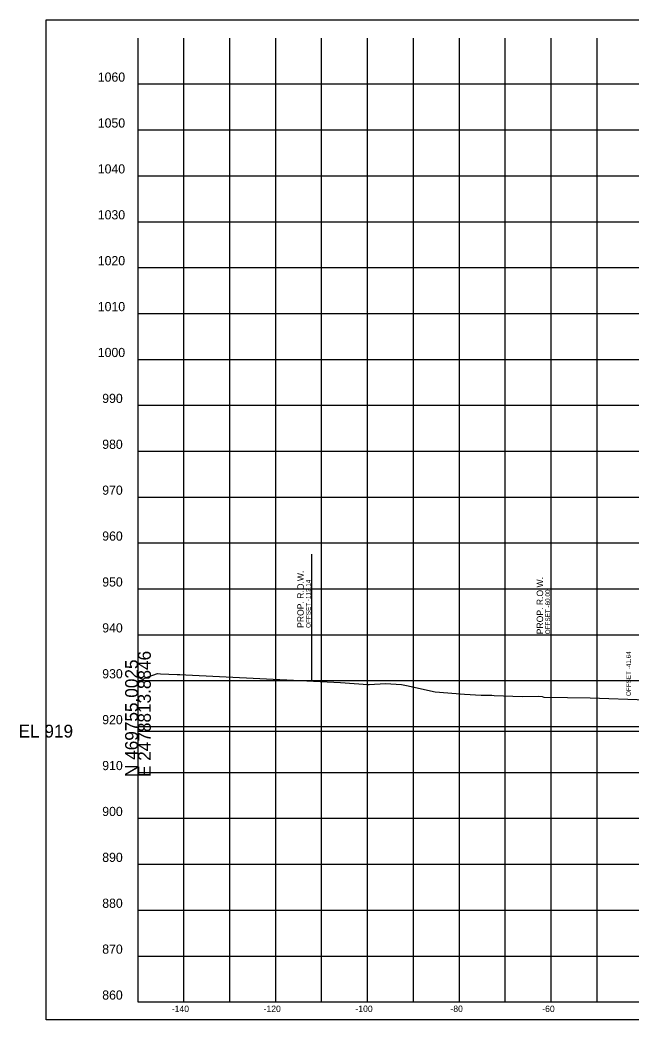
# Model space of a CAD drawing. Extents: x -26 to 2478923, y -10 to 469990.
# Drawn here: x -25.7 to 107.6, y 3437.1 to 3654.9 of the extents above; entities that cross this region are included whole.
import ezdxf

# ---------------------------------------------------------------- set-up
doc = ezdxf.new("R2010")
doc.units = 0
for name, color, linetype in [('DESIGN - ROW - Right-of-Way and Easement Labels', 7, 'Continuous'), ('DESIGN - ROW - Right-of-Way Linework', 7, 'Continuous'), ('DESIGN - SHEET - Corner Text', 7, 'Continuous'), ('DESIGN - SHEET - Light Grid', 7, 'Continuous'), ('DESIGN - SHEET - Linework', 7, 'Continuous'), ('DESIGN - SHEET - Plot Shape', 7, 'Continuous'), ('DESIGN - TYPICAL - Slope Tie Text', 7, 'Continuous'), ('SURVEY - GROUND - Top of Ground', 7, 'Continuous')]:
    doc.layers.add(name, color=color, linetype=linetype)

msp = doc.modelspace()

# ---------------------------------------------------------------- linework, layer by layer
at = {"layer": 'DESIGN - ROW - Right-of-Way Linework'}
for p, q in [((37.86, 3510.88), (37.86, 3538.56)), ((90, 3507.36), (90, 3537.04))]:
    msp.add_line(p, q, dxfattribs=at)
at = {"layer": 'DESIGN - SHEET - Light Grid'}
msp.add_line((0, 3500), (150, 3500), dxfattribs=at)
at = {"layer": 'DESIGN - SHEET - Linework'}
for p, q in [((10, 3441), (10, 3651)), ((10, 3441), (10, 3651)), ((10, 3441), (10, 3651)), ((10, 3441), (10, 3651)), ((20, 3441), (20, 3651)), ((20, 3441), (20, 3651)), ((20, 3441), (20, 3651)), ((20, 3441), (20, 3651)), ((30, 3441), (30, 3651)), ((30, 3441), (30, 3651)), ((30, 3441), (30, 3651)), ((30, 3441), (30, 3651)), ((40, 3441), (40, 3651)), ((40, 3441), (40, 3651)), ((40, 3441), (40, 3651)), ((40, 3441), (40, 3651)), ((50, 3441), (50, 3651)), ((50, 3441), (50, 3651)), ((50, 3441), (50, 3651)), ((50, 3441), (50, 3651)), ((60, 3441), (60, 3651)), ((60, 3441), (60, 3651)), ((60, 3441), (60, 3651)), ((60, 3441), (60, 3651)), ((70, 3441), (70, 3651)), ((70, 3441), (70, 3651)), ((70, 3441), (70, 3651)), ((70, 3441), (70, 3651)), ((80, 3441), (80, 3651)), ((80, 3441), (80, 3651)), ((80, 3441), (80, 3651)), ((80, 3441), (80, 3651)), ((90, 3441), (90, 3651)), ((90, 3441), (90, 3651)), ((90, 3441), (90, 3651)), ((90, 3441), (90, 3651)), ((100, 3441), (100, 3651)), ((100, 3441), (100, 3651)), ((100, 3441), (100, 3651)), ((100, 3441), (100, 3651)), ((0, 3641), (300, 3641)), ((0, 3641), (300, 3641)), ((0, 3641), (300, 3641)), ((0, 3641), (300, 3641)), ((0, 3631), (300, 3631)), ((0, 3631), (300, 3631)), ((0, 3631), (300, 3631)), ((0, 3631), (300, 3631)), ((0, 3621), (300, 3621)), ((0, 3621), (300, 3621)), ((0, 3621), (300, 3621)), ((0, 3621), (300, 3621)), ((0, 3611), (300, 3611)), ((0, 3611), (300, 3611)), ((0, 3611), (300, 3611)), ((0, 3611), (300, 3611)), ((0, 3601), (300, 3601)), ((0, 3601), (300, 3601)), ((0, 3601), (300, 3601)), ((0, 3601), (300, 3601)), ((0, 3591), (300, 3591)), ((0, 3591), (300, 3591)), ((0, 3591), (300, 3591)), ((0, 3591), (300, 3591)), ((0, 3581), (300, 3581)), ((0, 3581), (300, 3581)), ((0, 3581), (300, 3581)), ((0, 3581), (300, 3581)), ((0, 3571), (300, 3571)), ((0, 3571), (300, 3571)), ((0, 3571), (300, 3571)), ((0, 3571), (300, 3571)), ((0, 3561), (300, 3561)), ((0, 3561), (300, 3561)), ((0, 3561), (300, 3561)), ((0, 3561), (300, 3561)), ((0, 3551), (300, 3551)), ((0, 3551), (300, 3551)), ((0, 3551), (300, 3551)), ((0, 3551), (300, 3551)), ((0, 3541), (300, 3541)), ((0, 3541), (300, 3541)), ((0, 3541), (300, 3541)), ((0, 3541), (300, 3541)), ((0, 3531), (300, 3531)), ((0, 3531), (300, 3531)), ((0, 3531), (300, 3531)), ((0, 3531), (300, 3531)), ((0, 3521), (300, 3521)), ((0, 3521), (300, 3521)), ((0, 3521), (300, 3521)), ((0, 3521), (300, 3521)), ((0, 3511), (300, 3511)), ((0, 3511), (300, 3511)), ((0, 3511), (300, 3511)), ((0, 3511), (300, 3511)), ((0, 3501), (300, 3501)), ((0, 3501), (300, 3501)), ((0, 3501), (300, 3501)), ((0, 3501), (300, 3501)), ((0, 3491), (300, 3491)), ((0, 3491), (300, 3491)), ((0, 3491), (300, 3491)), ((0, 3491), (300, 3491)), ((0, 3481), (300, 3481)), ((0, 3481), (300, 3481)), ((0, 3481), (300, 3481)), ((0, 3481), (300, 3481)), ((0, 3471), (300, 3471)), ((0, 3471), (300, 3471)), ((0, 3471), (300, 3471)), ((0, 3471), (300, 3471)), ((0, 3461), (300, 3461)), ((0, 3461), (300, 3461)), ((0, 3461), (300, 3461)), ((0, 3461), (300, 3461)), ((0, 3451), (300, 3451)), ((0, 3451), (300, 3451)), ((0, 3451), (300, 3451)), ((0, 3451), (300, 3451))]:
    msp.add_line(p, q, dxfattribs=at)
msp.add_lwpolyline([(0, 3651), (0, 3441), (300, 3441), (300, 3651)], dxfattribs=at)
msp.add_lwpolyline([(0, 3651), (0, 3441), (300, 3441), (300, 3651)], dxfattribs=at)
msp.add_lwpolyline([(0, 3651), (0, 3441), (300, 3441), (300, 3651)], dxfattribs=at)
msp.add_lwpolyline([(0, 3651), (0, 3441), (300, 3441), (300, 3651)], dxfattribs=at)
at = {"layer": 'DESIGN - SHEET - Plot Shape'}
msp.add_lwpolyline([(-20, 3654.94), (320, 3654.94), (320, 3437.06), (-20, 3437.06)], close=True, dxfattribs=at)
msp.add_lwpolyline([(-20, 3654.94), (320, 3654.94), (320, 3437.06), (-20, 3437.06)], close=True, dxfattribs=at)
msp.add_lwpolyline([(-20, 3654.94), (320, 3654.94), (320, 3437.06), (-20, 3437.06)], close=True, dxfattribs=at)
msp.add_lwpolyline([(-20, 3654.94), (320, 3654.94), (320, 3437.06), (-20, 3437.06)], close=True, dxfattribs=at)
at = {"layer": 'SURVEY - GROUND - Top of Ground'}
msp.add_line((10.46, 3512.27), (44.08, 3510.56), dxfattribs=at)
for points in [[(0, 3511.78), (1.14, 3511.23), (1.44, 3511.54), (4.22, 3512.52), (4.91, 3512.49), (8.56, 3512.35), (9.1, 3512.32), (10.46, 3512.27)], [(44.08, 3510.56), (50.04, 3510.14), (50.36, 3510.16), (53.9, 3510.35), (57.39, 3510.17), (58.48, 3509.94), (64.7, 3508.58), (71.11, 3508.03), (74.73, 3507.86), (77.06, 3507.82), (77.59, 3507.79), (83.71, 3507.55), (87.32, 3507.61), (88.01, 3507.58), (88.37, 3507.37), (93.55, 3507.36), (98.52, 3507.24), (110.74, 3506.8)]]:
    msp.add_lwpolyline(points, dxfattribs=at)

# ---------------------------------------------------------------- texts
at = {"layer": 'DESIGN - ROW - Right-of-Way and Easement Labels'}
for s, height, p in [('PROP. R.O.W.', 1.4, (36.11, 3522.49)), ('OFFSET -112.14', 1, (37.61, 3522.49)), ('PROP. R.O.W.', 1.4, (88.25, 3521.1)), ('OFFSET -60.00', 1, (89.75, 3521.1))]:
    msp.add_text(s, height=height, rotation=90, dxfattribs=at).set_placement(p)
at = {"layer": 'DESIGN - SHEET - Corner Text'}
for s, height, p in [('1060', 2, (-8.75, 3641.5)), ('1060', 2, (-8.75, 3641.5)), ('1060', 2, (-8.75, 3641.5)), ('1060', 2, (-8.75, 3641.5)), ('1050', 2, (-8.75, 3631.5)), ('1050', 2, (-8.75, 3631.5)), ('1050', 2, (-8.75, 3631.5)), ('1050', 2, (-8.75, 3631.5)), ('1040', 2, (-8.75, 3621.5)), ('1040', 2, (-8.75, 3621.5)), ('1040', 2, (-8.75, 3621.5)), ('1040', 2, (-8.75, 3621.5)), ('1030', 2, (-8.75, 3611.5)), ('1030', 2, (-8.75, 3611.5)), ('1030', 2, (-8.75, 3611.5)), ('1030', 2, (-8.75, 3611.5)), ('1020', 2, (-8.75, 3601.5)), ('1020', 2, (-8.75, 3601.5)), ('1020', 2, (-8.75, 3601.5)), ('1020', 2, (-8.75, 3601.5)), ('1010', 2, (-8.75, 3591.5)), ('1010', 2, (-8.75, 3591.5)), ('1010', 2, (-8.75, 3591.5)), ('1010', 2, (-8.75, 3591.5)), ('1000', 2, (-8.75, 3581.5)), ('1000', 2, (-8.75, 3581.5)), ('1000', 2, (-8.75, 3581.5)), ('1000', 2, (-8.75, 3581.5)), ('990', 2, (-7.78, 3571.5)), ('990', 2, (-7.78, 3571.5)), ('990', 2, (-7.78, 3571.5)), ('990', 2, (-7.78, 3571.5)), ('980', 2, (-7.78, 3561.5)), ('980', 2, (-7.78, 3561.5)), ('980', 2, (-7.78, 3561.5)), ('980', 2, (-7.78, 3561.5)), ('970', 2, (-7.78, 3551.5)), ('970', 2, (-7.78, 3551.5)), ('970', 2, (-7.78, 3551.5)), ('970', 2, (-7.78, 3551.5)), ('960', 2, (-7.78, 3541.5)), ('960', 2, (-7.78, 3541.5)), ('960', 2, (-7.78, 3541.5)), ('960', 2, (-7.78, 3541.5)), ('950', 2, (-7.78, 3531.5)), ('950', 2, (-7.78, 3531.5)), ('950', 2, (-7.78, 3531.5)), ('950', 2, (-7.78, 3531.5)), ('940', 2, (-7.78, 3521.5)), ('940', 2, (-7.78, 3521.5)), ('940', 2, (-7.78, 3521.5)), ('940', 2, (-7.78, 3521.5)), ('930', 2, (-7.78, 3511.5)), ('930', 2, (-7.78, 3511.5)), ('930', 2, (-7.78, 3511.5)), ('930', 2, (-7.78, 3511.5)), ('920', 2, (-7.78, 3501.5)), ('920', 2, (-7.78, 3501.5)), ('920', 2, (-7.78, 3501.5)), ('920', 2, (-7.78, 3501.5)), ('910', 2, (-7.78, 3491.5)), ('910', 2, (-7.78, 3491.5)), ('910', 2, (-7.78, 3491.5)), ('910', 2, (-7.78, 3491.5)), ('900', 2, (-7.78, 3481.5)), ('900', 2, (-7.78, 3481.5)), ('900', 2, (-7.78, 3481.5)), ('900', 2, (-7.78, 3481.5)), ('890', 2, (-7.78, 3471.5)), ('890', 2, (-7.78, 3471.5)), ('890', 2, (-7.78, 3471.5)), ('890', 2, (-7.78, 3471.5)), ('880', 2, (-7.78, 3461.5)), ('880', 2, (-7.78, 3461.5)), ('880', 2, (-7.78, 3461.5)), ('880', 2, (-7.78, 3461.5)), ('870', 2, (-7.78, 3451.5)), ('870', 2, (-7.78, 3451.5)), ('870', 2, (-7.78, 3451.5)), ('870', 2, (-7.78, 3451.5)), ('860', 2, (-7.78, 3441.5)), ('860', 2, (-7.78, 3441.5)), ('860', 2, (-7.78, 3441.5)), ('860', 2, (-7.78, 3441.5)), ('-140', 1.4, (7.37, 3438.8)), ('-140', 1.4, (7.37, 3438.8)), ('-140', 1.4, (7.37, 3438.8)), ('-140', 1.4, (7.37, 3438.8)), ('-120', 1.4, (27.37, 3438.8)), ('-120', 1.4, (27.37, 3438.8)), ('-120', 1.4, (27.37, 3438.8)), ('-120', 1.4, (27.37, 3438.8)), ('-100', 1.4, (47.37, 3438.8)), ('-100', 1.4, (47.37, 3438.8)), ('-100', 1.4, (47.37, 3438.8)), ('-100', 1.4, (47.37, 3438.8)), ('-80', 1.4, (68.06, 3438.8)), ('-80', 1.4, (68.06, 3438.8)), ('-80', 1.4, (68.06, 3438.8)), ('-80', 1.4, (68.06, 3438.8)), ('-60', 1.4, (88.06, 3438.8)), ('-60', 1.4, (88.06, 3438.8)), ('-60', 1.4, (88.06, 3438.8)), ('-60', 1.4, (88.06, 3438.8))]:
    msp.add_text(s, height=height, dxfattribs=at).set_placement(p)
at = {"layer": 'DESIGN - SHEET - Light Grid'}
for s, p in [('E 2478813.8846', (2.8, 3490)), ('N 469755.0025', (0, 3490))]:
    msp.add_text(s, height=2.8, rotation=90, dxfattribs=at).set_placement(p)
msp.add_text('EL 919', height=2.8, dxfattribs=at).set_placement((-26, 3498.6))
at = {"layer": 'DESIGN - TYPICAL - Slope Tie Text'}
msp.add_text('OFFSET -41.64', height=1, rotation=90, dxfattribs=at).set_placement((107.36, 3507.64))

doc.saveas('drawing.dxf')
